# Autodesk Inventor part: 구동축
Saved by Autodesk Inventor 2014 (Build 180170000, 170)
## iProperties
Created: 2026-05
Part Number: 구동축
Material: 강철, 탄소
Document SubType Name: Modeling
Designer: dg
Density: 7.87 g/cm^3
Appearance: 반연마
Mass: 347.491 g
Surface Area: 104.661 cm^2
Volume: 44.1539 cm^3
Author: jhkim
Creation Date: 2026-04-23
Sending System: Autodesk Inventor 2027
Preprocessor: ST-DEVELOPER v20.1
Author: dg
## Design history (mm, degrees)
node "구동축1"
node "솔리드1"
node "기준1"
